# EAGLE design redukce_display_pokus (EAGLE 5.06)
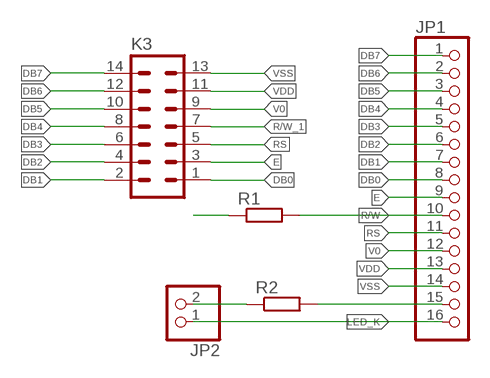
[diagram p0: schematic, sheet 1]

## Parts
JP1  PINHD-1X16  [1X16]
JP2  PINHD-1X2  [1X02]
K3  14V  [14V]
R1  R-EU_0207/10  [0207/10]
R2  R-EU_0207/10  [0207/10]

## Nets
DB0: JP1.8 K3.1
DB1: JP1.7 K3.2
DB2: JP1.6 K3.4
DB3: JP1.5 K3.6
DB4: JP1.4 K3.8
DB5: JP1.3 K3.10
DB6: JP1.2 K3.12
DB7: JP1.1 K3.14
E: JP1.9 K3.3
LED_K: JP1.16 JP2.1
N$1: JP1.15 R2.2
N$2: JP2.2 R2.1
R/W: JP1.10 R1.2
R/W_1: K3.7 R1.1
RS: JP1.11 K3.5
V0: JP1.12 K3.9
VDD: JP1.13 K3.11
VSS: JP1.14 K3.13

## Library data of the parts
JP1 = pinhead:PINHD-1X16: PIN HEADER
JP2 = pinhead:PINHD-1X2: PIN HEADER
K3 = con-harting-v:14V: CONNECTOR
R1 R2 = rcl:R-EU_: RESISTOR, European symbol

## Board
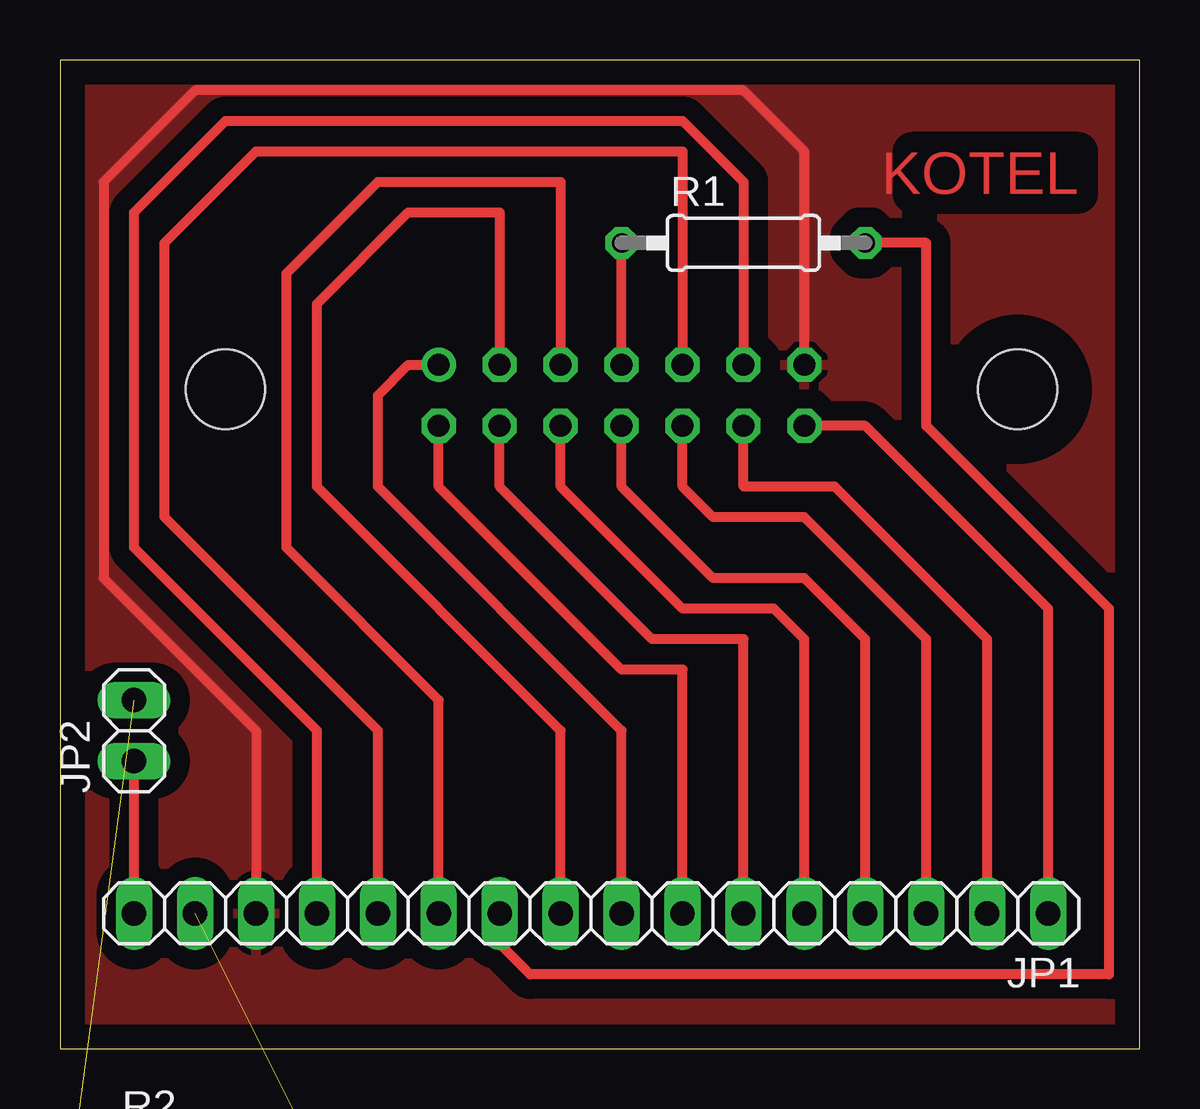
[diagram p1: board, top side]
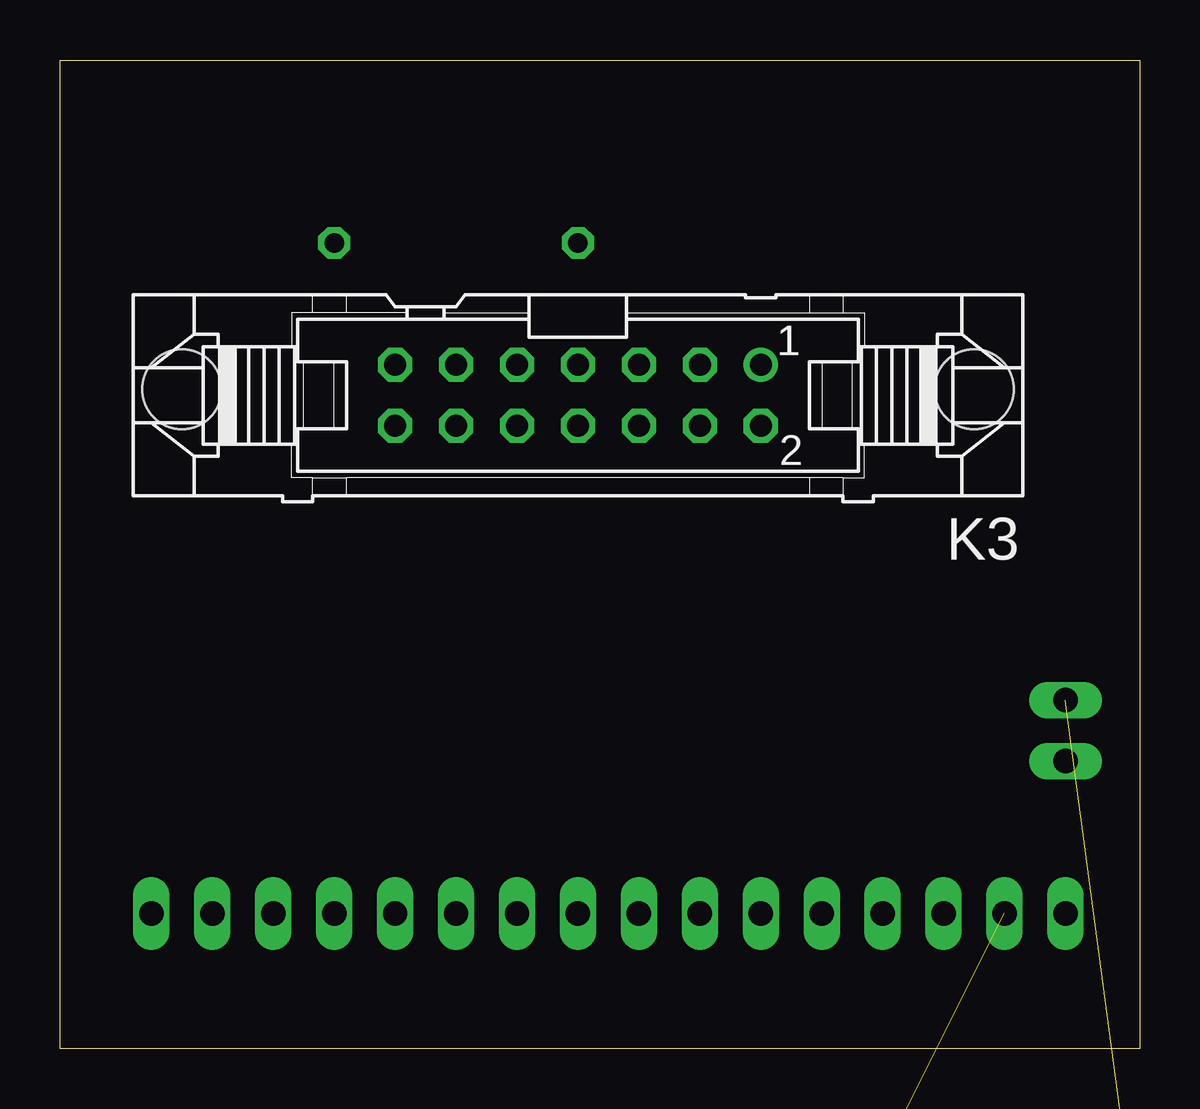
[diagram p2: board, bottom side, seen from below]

Size 45 x 41.19 mm. Coordinates in mm from the lower left corner, seen from the top.
Outline: 45,41.19 0,41.19 0,0 45,0 45,41.19
Copper layers (1*16): Top 0.035mm / dielectric 1.5mm / Bottom 0.035mm
Design rules "default": minimum track width 10mil, minimum drill 24mil, track to track 8mil, track to pad 8mil, pad to pad 8mil, via to via 8mil, smd to smd 8mil, copper to edge 40mil, drill to drill 8mil, minimum pad ring 10mil, minimum via ring 8mil, stop-mask expansion 4mil, vias tented up to drill 0mil, thermal gap 10mil

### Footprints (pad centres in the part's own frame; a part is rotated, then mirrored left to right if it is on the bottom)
1X16 = drill 1.016 long: 1 -19.05,0; 2 -16.51,0; 3 -13.97,0; 4 -11.43,0; 5 -8.89,0; 6 -6.35,0; 7 -3.81,0; 8 -1.27,0; 9 1.27,0; 10 3.81,0; 11 6.35,0; 12 8.89,0; 13 11.43,0; 14 13.97,0; 15 16.51,0; 16 19.05,0
1X02 = drill 1.016 long: 1 -1.27,0; 2 1.27,0
14V = drill 0.914 round: 1 -7.62,-1.27 | drill 0.914 octagon: 2 -7.62,1.27; 3 -5.08,-1.27; 4 -5.08,1.27; 5 -2.54,-1.27; 6 -2.54,1.27; 7 0,-1.27; 8 0,1.27; 9 2.54,-1.27; 10 2.54,1.27; 11 5.08,-1.27; 12 5.08,1.27; 13 7.62,-1.27; 14 7.62,1.27 | hole 3.302: 16.51,-0.254; -16.51,-0.254
0207/10 = drill 0.813 octagon: 1 -5.08,0; 2 5.08,0

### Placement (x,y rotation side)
JP1  22.14,5.63 180 top
JP2  3.09,13.25 90 top
K3  23.41,27.22 180 bottom
R1  28.49,33.57 0 top
R2  not placed on the board

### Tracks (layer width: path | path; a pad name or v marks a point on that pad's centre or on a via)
DB0
  Top 0.406: JP1.8 23.41,13.25 13.25,23.41 13.25,27.22 14.52,28.49 K3.1
DB1
  Top 0.406: JP1.7 25.95,15.79 23.41,15.79 15.79,23.41 K3.2
DB2
  Top 0.406: JP1.6 28.49,17.06 24.68,17.06 18.33,23.41 K3.4
DB3
  Top 0.406: JP1.5 31.03,17.06 29.76,18.33 25.95,18.33 20.87,23.41 K3.6
DB4
  Top 0.406: JP1.4 33.57,17.06 31.03,19.6 27.22,19.6 23.41,23.41 K3.8
DB5
  Top 0.406: JP1.3 36.11,17.06 31.03,22.14 27.22,22.14 25.95,23.41 K3.10
DB6
  Top 0.406: JP1.2 38.65,17.06 32.3,23.41 28.49,23.41 K3.12
DB7
  Top 0.406: K3.14 33.57,25.95 41.19,18.33 JP1.1
E
  Top 0.406: K3.3 18.33,34.84 14.52,34.84 10.71,31.03 10.71,23.41 20.87,13.25 JP1.9
LED_K
  Top 0.406: JP1.16 JP2.1
N$1  (1 unrouted)
N$2  (1 unrouted)
R/W
  Top 0.406: R1.2 36.11,33.57 36.11,25.95 43.73,18.33 43.73,3.09 19.6,3.09 18.33,4.36 JP1.10
R/W_1
  Top 0.406: K3.7 R1.1
RS
  Top 0.406: K3.5 20.87,36.11 13.25,36.11 9.44,32.3 9.44,20.87 15.79,14.52 JP1.11
V0
  Top 0.406: K3.9 25.95,37.38 8.17,37.38 4.36,33.57 4.36,22.14 13.25,13.25 JP1.12
VDD
  Top 0.406: JP1.13 10.71,13.25 3.09,20.87 3.09,34.84 6.9,38.65 25.95,38.65 28.49,36.11 K3.11
VSS
  Top 0.406: K3.13 31.03,37.38 28.49,39.92 5.63,39.92 1.82,36.11 1.82,19.6 8.17,13.25 JP1.14
  pour Top (isolate 0.813): 45,0 0,0 0,41.19 45,41.19

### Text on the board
Top: KOTEL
